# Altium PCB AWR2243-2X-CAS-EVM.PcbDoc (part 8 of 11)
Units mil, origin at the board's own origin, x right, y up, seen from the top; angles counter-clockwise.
Board outline 5118.11 x 3937.01 mil, 8 copper layers (Layer 1 - Top Layer, Layer 2 - GND, Layer 3 - Signal (Sensitive), Layer 4 - GND / Signal, Layer 5 - Signal, Layer 6 - PWR / Signal, Layer 7 - GND, Layer 8 - Bottom Layer), stack 54.8 mil thick; 629 components, 407 nets, 2243 pads, 3950 vias.
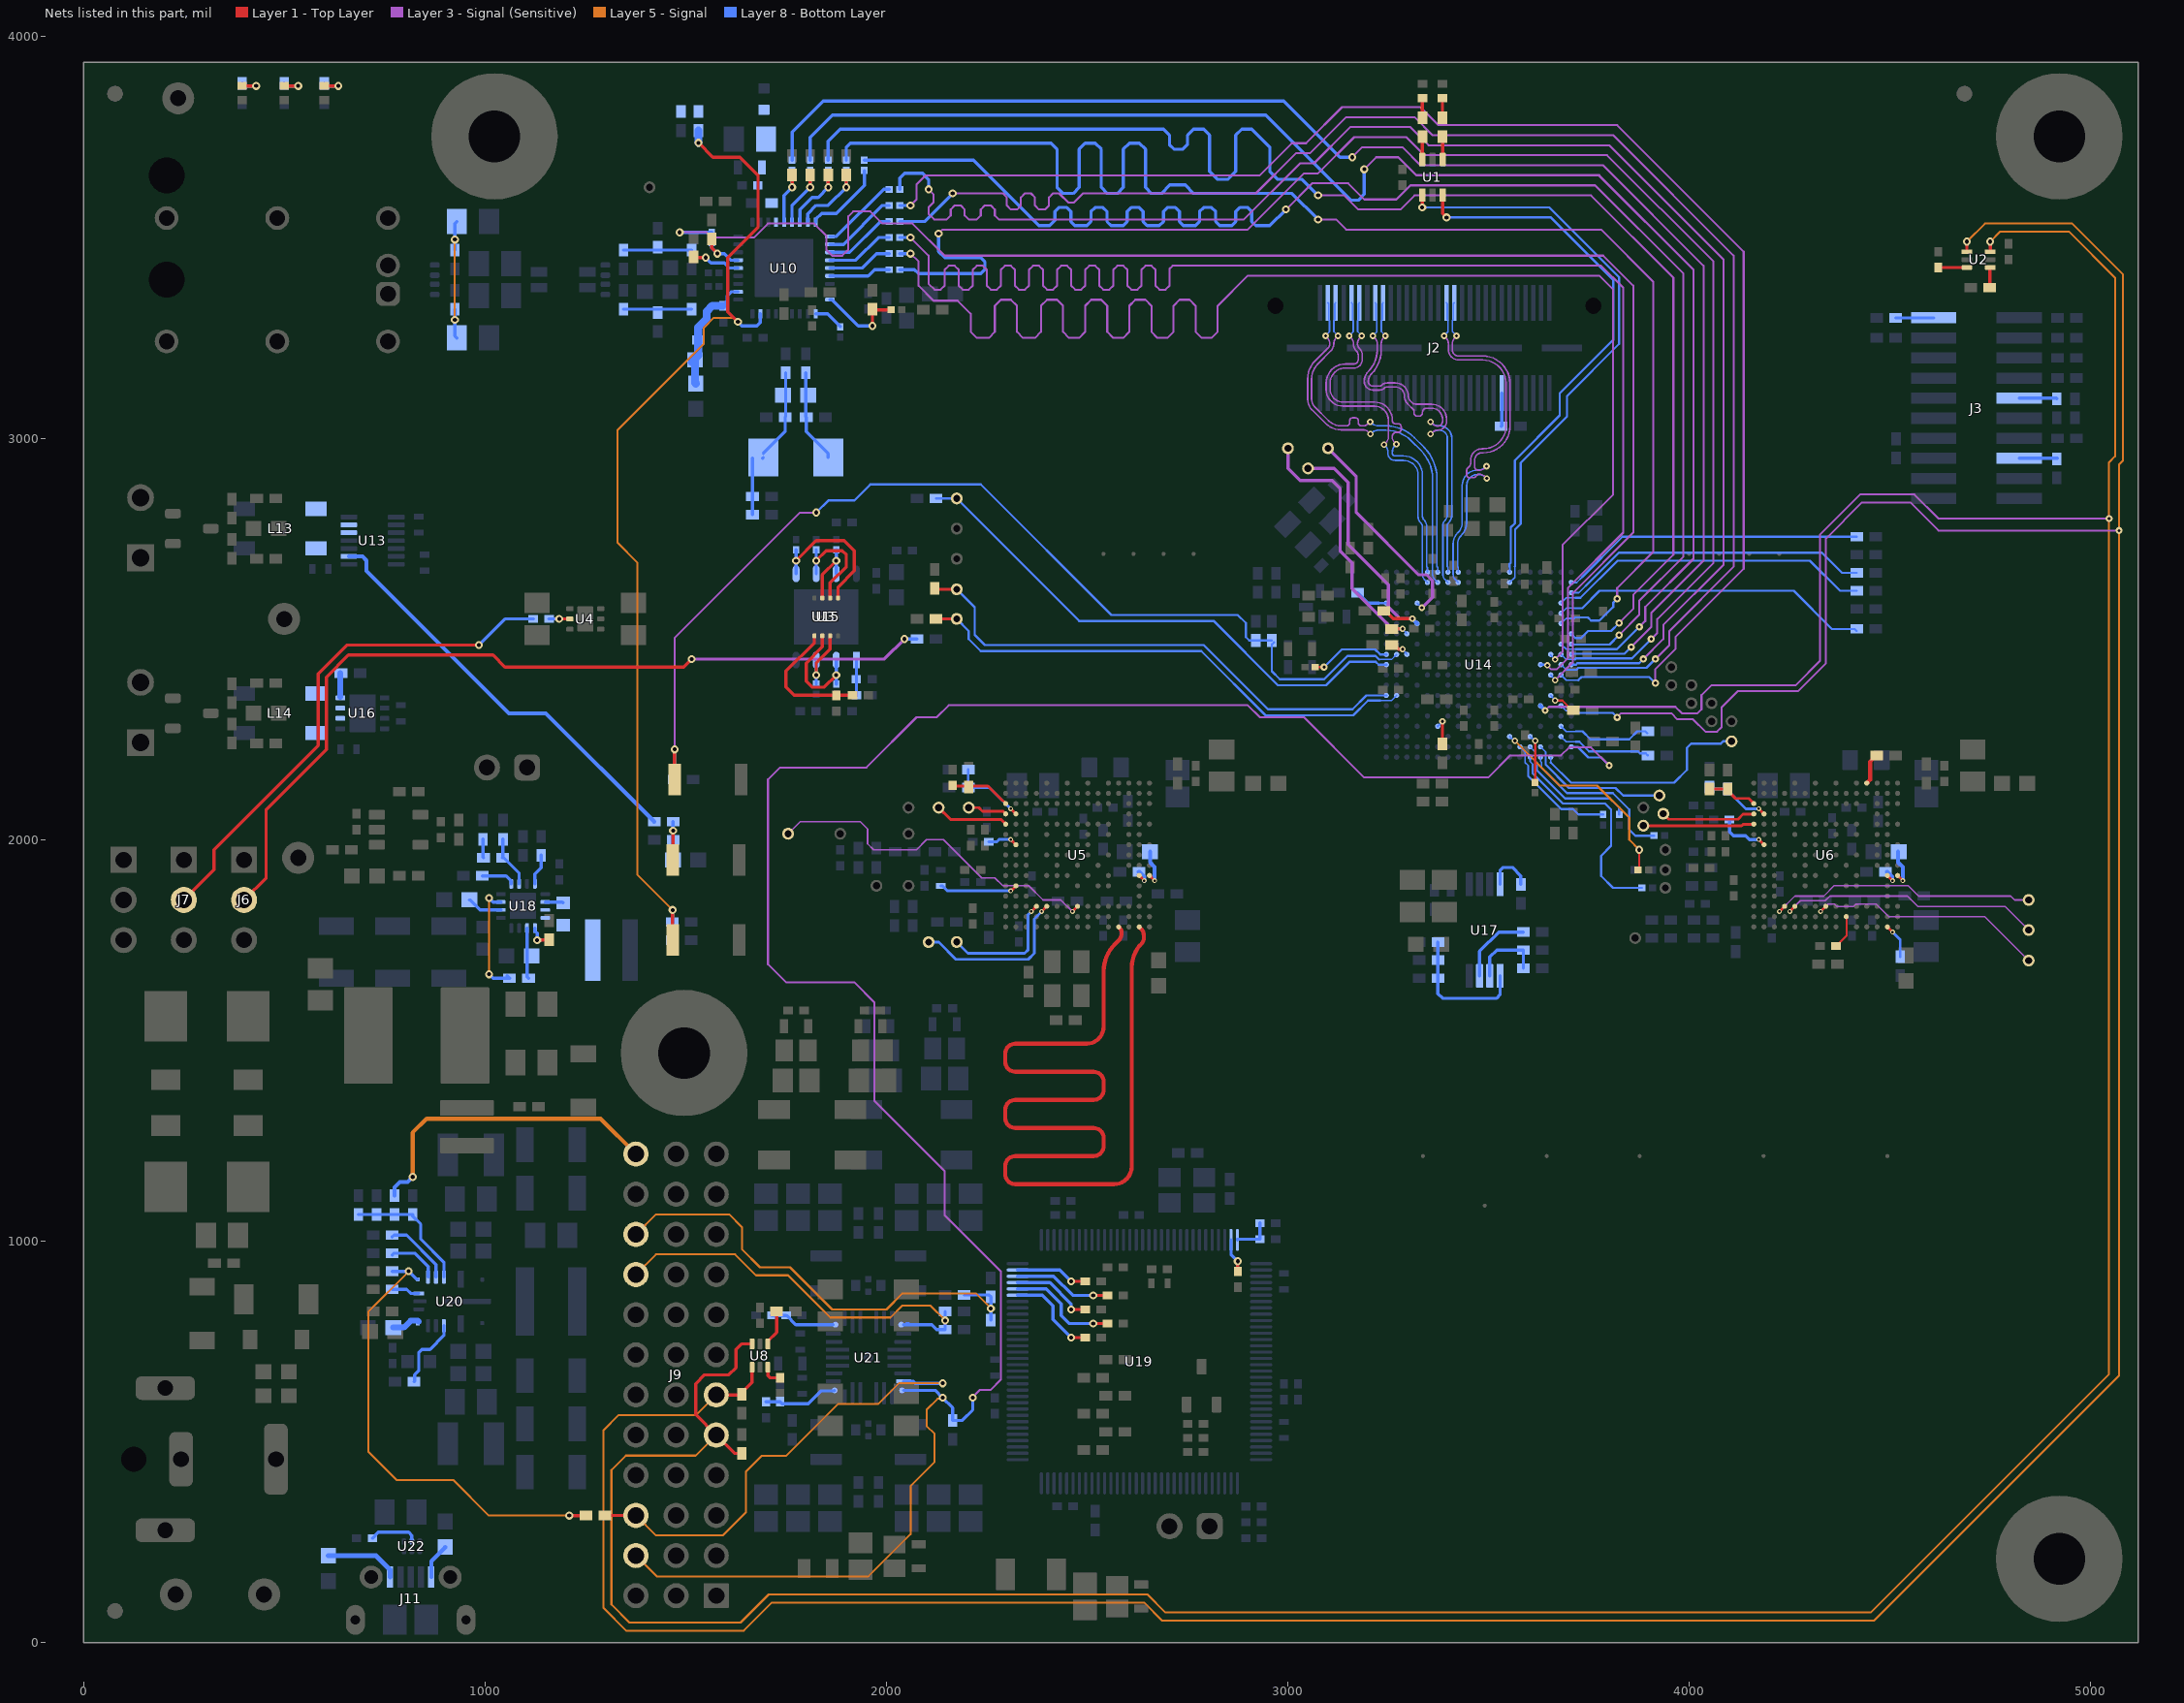
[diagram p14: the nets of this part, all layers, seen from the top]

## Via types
v1: diameter 13.78, hole 5.91, Layer 1 - Top Layer to Layer 2 - GND, tented top, 2104 vias
v2: diameter 20, hole 10, Layer 1 - Top Layer to Layer 8 - Bottom Layer, tented both sides, 831 vias
v3: diameter 7.87, hole 3.94, Layer 1 - Top Layer to Layer 2 - GND, tented top, 510 vias
v4: diameter 12, hole 6, Layer 1 - Top Layer to Layer 8 - Bottom Layer, tented both sides, 176 vias
v5: diameter 16, hole 8, Layer 1 - Top Layer to Layer 8 - Bottom Layer, tented both sides, 138 vias
v6: diameter 13.78, hole 5.91, Layer 1 - Top Layer to Layer 2 - GND, tented both sides, 88 vias
v7: diameter 18, hole 8, Layer 1 - Top Layer to Layer 8 - Bottom Layer, tented both sides, 41 vias
v8: diameter 22, hole 12, Layer 1 - Top Layer to Layer 8 - Bottom Layer, tented both sides, 36 vias
v9: diameter 19.68, hole 7.87, Layer 1 - Top Layer to Layer 8 - Bottom Layer, tented both sides, 26 vias

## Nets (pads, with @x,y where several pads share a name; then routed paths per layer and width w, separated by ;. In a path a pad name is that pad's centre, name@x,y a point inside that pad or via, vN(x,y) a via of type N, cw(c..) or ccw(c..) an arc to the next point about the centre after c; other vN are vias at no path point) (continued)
NetC98_1: C98.1 C99.2 C243.1 C244.1 FB1.2 R87.1 R88.1 U10.22
NetC100_2: C100.2 C101.1 R100.2 | length 170
  Layer 8 - Bottom Layer w8: R100.2@1345,3468.62 C101.1@1515,3468.62
NetC105_2: C105.2 C108.1 R106.1 | length 170
  Layer 8 - Bottom Layer w8: R106.1@1345,3321.38 C105.2@1515,3321.38
NetC107_2: C107.2 C110.1 C242.1 R237.2 U10.11 | length 307.4
  Layer 8 - Bottom Layer w8: C107.2@1590.24,3331.69 1591.69,3331.69 1603,3343 1603,3355 1612.94,3364.94 U10.11@1630.83,3364.94
  Layer 8 - Bottom Layer w20: C110.1@1515,3190 1531.38,3206.38 C242.1@1531.38,3245 1531.38,3276.38 1552,3297 1552,3316 1566,3330 C107.2@1592,3330 ; C110.1@1523.5,3195 1523.5,3140.11 ccw(c1528.61,3140.11) R237.2@1525,3136.5
NetC109_1: C109.1 R96.2 R101.1 R107.1 | length 346.9
  Layer 5 - Signal w5: v2(925,3295) v2(925,3495)
  Layer 8 - Bottom Layer w8: R107.1@925,3321.38 v2(925,3295) 925,3255 C109.1@930,3250 ; R101.1@925,3468.62 v2(925,3495) 925,3535 R96.2@930,3540
NetC113_1: C113.1 R115.1 R119.2 Y2.1 | length 234.5
  Layer 8 - Bottom Layer w8: R115.1@1799,3163.38 1799,3053.38 C113.1@1800.38,3052 1800.38,3016.17 1854.71,2961.84 Y2.1@1854.71,2952
NetC114_1: C114.1 R116.2 R119.1 R126.2 R129.2 Y2.2 | length 367.4
  Layer 8 - Bottom Layer w8: R129.2@1666.38,2810 R126.2@1666.38,2855 Y2.2@1666.38,2950.09 ; Y2.2@1691.38,2950.09 Y2.2@1693.29,2952 ; Y2.2@1693.29,2961.84 1747.62,3016.17 C114.1@1747.62,3052 1749,3053.38 R116.2@1749,3163.38
NetC124_1: C124.1 U14.T1 | length 81.9
  Layer 8 - Bottom Layer w5.5: 3226.58,2589.69 U14.T1@3245.08,2589.69
  Layer 8 - Bottom Layer w8: C124.1@3173.62,2615 3198.94,2589.69 3226.58,2589.69
NetC137_1: C137.1 R142.2 R143.2 S1.1 U14.L2 | length 2680.9
  Layer 1 - Top Layer w8: S1.1@1472.32,2150 v2(1472.32,2225)
  Layer 3 - Signal (Sensitive) w5: v2(1472.32,2225) 1472.32,2502.32 1785,2815 v2(1825,2815)
  Layer 8 - Bottom Layer w4: 3227.18,2448.94 3257.87,2448.94 U14.L2@3270.67,2461.73
  Layer 8 - Bottom Layer w5.5: v2(1825,2815) 1855,2845 1920,2845 1960,2885 2235,2885 2560,2560 2875,2560 2895,2540 2895,2505 2903.62,2496.38 R143.2@2920,2496.38 R142.2@2960,2496.38 ; R142.2@2965,2491.38 2960,2486.38 2960,2420 2980,2400 3090,2400 3148,2458 3218.12,2458 3227.18,2448.94
  Layer 8 - Bottom Layer w8: C137.1@1471.38,2150 1472.32,2150.94 v2(1472.32,2225)
NetC144_1: C144.1 R177.2 U18.14 | length 131.3
  Layer 8 - Bottom Layer w8: C144.1@1045,2001.38 1045,1956.38 R177.2@1043.62,1955 1047.56,1955 1085,1917.56 1085,1890.28 U18.14@1085.16,1890.12
NetC145_1: C145.1 R177.1 | length 46.9
  Layer 8 - Bottom Layer w8: C145.1@995,2001.38 995,1956.38 R177.1@996.38,1955
NetC150_1: C150.1 U6.A10 | length 94.8
  Layer 1 - Top Layer w7: U6.A10@4518.5,1910.83 v4(4531.3,1898.03)
  Layer 8 - Bottom Layer w10: C150.1@4519.88,1970 4519.88,1943.5 4531.3,1932.09 v4(4531.3,1898.03)
NetC151_1: C151.1 U5.A10 | length 94.8
  Layer 1 - Top Layer w7: U5.A10@2655.12,1910.83 v4(2667.91,1898.03)
  Layer 8 - Bottom Layer w10: C151.1@2656.5,1970 2656.5,1943.5 2667.91,1932.09 v4(2667.91,1898.03)
NetC152_1: C152.1 R163.1 R169.1 S2.1 | length 168.1
  Layer 1 - Top Layer w8: S2.1@1467.32,1950 1468.62,1951.3 v2(1468.62,2022.5)
  Layer 8 - Bottom Layer w8: C152.1@1468.5,1950 1468.62,1950.12 R169.1@1468.62,2000 v2(1468.62,2022.5) R163.1@1468.62,2045
NetC154_1: C154.1 U6.B10 | length 46
  Layer 1 - Top Layer w7: U6.B10@4492.91,1910.83 v4(4505.71,1898.03)
  Layer 8 - Bottom Layer w10: C154.1@4492.01,1920 4493.39,1920 4505.33,1908.06 v4@4505.33,1898.41
NetC155_1: C155.1 U5.B10 | length 46.5
  Layer 1 - Top Layer w7: U5.B10@2629.53,1910.83 v4(2642.32,1898.03)
  Layer 8 - Bottom Layer w10: C155.1@2628.62,1920 2630,1920 2641.94,1908.06 2641.94,1898.41 v4(2642.32,1898.03)
NetC162_1: C162.1 U18.10 | length 88.7
  Layer 8 - Bottom Layer w8: C162.1@961.5,1850 962.48,1850 987.32,1825.16 U18.10@1039.88,1825.16
NetC167_1: C167.1 L15.2 U18.3 U18.4
NetC167_2: C167.2 U18.2 | length 45.8
  Layer 8 - Bottom Layer w8: U18.2@1150.12,1844.84 1192.72,1844.84 C167.2@1195,1842.56
NetC182_2: C182.2 R87.2 R194.2 S3.2 U10.8 | length 2549.3
  Layer 1 - Top Layer w8: S3.2@1467.32,1750 v2(1467.32,1825) ; v2(1531.77,3736) 1567.77,3700 1635,3700 1680,3655 1680,3525 1605,3450 1605,3315 v2(1630,3290)
  Layer 5 - Signal w5: v2(1467.32,1825) 1380,1912.32 1380,2690 1330,2740 1330,3020 1545,3235 1545,3275 1570,3300 1620,3300 v2(1630,3290)
  Layer 8 - Bottom Layer w8: C182.2@1466.38,1750 1467.32,1750.94 v2(1467.32,1825) ; v2(1630,3290) 1640,3280 1677.35,3280 1685.94,3288.59 U10.8@1685.94,3309.83
  Layer 8 - Bottom Layer w20: v2(1531.77,3736) R87.2@1531.77,3766.38
NetC183_1: C183.1 R204.2 U18.6 | length 126.4
  Layer 8 - Bottom Layer w8: U18.6@1104.84,1779.88 1104.84,1658.78 R204.2@1108.62,1655
NetC208_2: C208.2 R212.1 U19.96 | length 98
  Layer 8 - Bottom Layer w8: U19.96@2874.09,1003.15 2874.09,1004.94 2874.16,1005 C208.2@2930.31,1005 R212.1@2930.31,1045
NetC211_2: C211.2 R220.1 U21.25 | length 164.1
  Layer 8 - Bottom Layer w8: R220.1@1714.68,815 C211.2@1750.31,815 ; C211.2@1748.35,814.33 1751.67,814.33 1774.31,791.69 U21.25@1867.4,791.69
NetC212_2: C212.2 U20.6 | length 71.4
  Layer 8 - Bottom Layer w15: C212.2@771.5,785 798,785 815,802 833,802 835,800
NetC223_2: C223.2 R223.1 U21.17 | length 187.5
  Layer 8 - Bottom Layer w8: R223.1@1699.68,600 1699.84,600.16 1734.84,600.16 C223.2@1735,600.31 1740.31,595 1805,595 1837.21,627.21 1869.87,627.21 U21.17@1871.03,628.37
NetD1_1: D1.1 R1.1 | length 48.7
  Layer 1 - Top Layer w8: R1.1@3335,3798.62 D1.1@3335,3847.28
NetD2_1: D2.1 R2.1 | length 48.7
  Layer 1 - Top Layer w8: R2.1@3385,3798.62 D2.1@3385,3847.28
NetD3_1: D3.1 R86.1 | length 72.4
  Layer 1 - Top Layer w8: D3.1@395,3877.72 v2(430,3877.72)
  Layer 8 - Bottom Layer w8: R86.1@395,3883.62 400.91,3877.72 v2(430,3877.72)
NetD4_1: D4.1 R85.1 | length 72.4
  Layer 1 - Top Layer w8: D4.1@500,3877.72 v2(535,3877.72)
  Layer 8 - Bottom Layer w8: R85.1@500,3883.62 505.91,3877.72 v2(535,3877.72)
NetD5_2: D5.2 R84.1 | length 72.4
  Layer 1 - Top Layer w8: D5.2@600,3877.72 v2(635,3877.72)
  Layer 8 - Bottom Layer w8: R84.1@600,3883.62 605.91,3877.72 v2(635,3877.72)
NetJ2_13: J2.13 R122.1 | length 82.6
  Layer 8 - Bottom Layer w8: R122.1@3531.38,3030 3532.32,3030.94 J2.13@3532.32,3112.2
NetJ6_2: J6.2 R146.1 | length 2175.5
  Layer 1 - Top Layer w8: J6.2@400,1850 455,1905 455,2075 605,2225 605,2405 660,2460 1020,2460 1050,2430 1495,2430 v2(1515,2450)
  Layer 3 - Signal (Sensitive) w8: v2(1515,2450) 1995,2450 v2(2045,2500)
  Layer 8 - Bottom Layer w8: v2(2045,2500) R146.1@2076.38,2500
NetJ7_2: J7.2 R144.1 | length 1294
  Layer 1 - Top Layer w8: J7.2@250,1850 325,1925 325,1975 585,2235 585,2413.28 656.72,2485 v2(985,2485)
  Layer 8 - Bottom Layer w8: v2(985,2485) 1050,2550 R144.1@1120.31,2550
NetJ9_30: J9.30 R216.1 R219.1 R241.1 | length 1193.3
  Layer 5 - Signal w5: J9.30@1375.98,1017.01 1425.98,1067 1608,1067 1640,1035 1640,980 1685,935 1760,935 1865,830 2000,830 2040,870 2222.5,870 v2(2260,832.5)
  Layer 8 - Bottom Layer w8: R241.1@2193.62,866 2255.38,866 R216.1@2260,861.38 v2(2260,832.5) R219.1@2260,803.62
NetJ11_1: J11.1 R229.1 | length 89.8
  Layer 8 - Bottom Layer w10: J11.1@866.18,163.15 866.18,202.7 901,237.52 R229.1@901,238.5
NetJ11_5: J11.5 R233.2 | length 186.5
  Layer 8 - Bottom Layer w12: R233.2@610,216.5 728.5,216.5 763.82,181.18 J11.5@763.82,163.15
NetL13_1: L13.1 U13.13
NetL13_2: L13.2 U13.12
NetL14_1: L14.1 U16.7
NetL14_2: L14.2 U16.6
NetR1_2: R1.2 U1.6 | length 57.3
  Layer 1 - Top Layer w8: U1.6@3334.41,3694.29 3334.7,3694.59 3334.7,3751.08 R1.2@3335,3751.38
NetR2_2: R2.2 U1.4 | length 57.3
  Layer 1 - Top Layer w8: R2.2@3385,3751.38 3385.3,3751.08 3385.3,3694.59 U1.4@3385.59,3694.29
NetR10_2: R10.2 U2.3 | length 70.9
  Layer 1 - Top Layer w8: R10.2@4620,3425.31 U2.3@4690.87,3425.32
NetR11_1: R11.1 R16.2 U10.36 | length 211.8
  Layer 1 - Top Layer w8: v2(1965,3280) R11.1@1965,3311.38 ; R11.1@1965,3321.38 1966.38,3320 R16.2@2012.01,3320
  Layer 8 - Bottom Layer w8: U10.36@1859.17,3345.26 1864.74,3345.26 1930,3280 v2(1965,3280)
NetR12_1: R12.1 U2.4 | length 51.6
  Layer 1 - Top Layer w8: U2.4@4749.13,3425.32 4748.56,3424.74 R12.1@4748.56,3375.57 ; R12.1@4748.56,3375.57 R12.1@4747.99,3375 R12.1@4748.56,3375.57
NetR25_1: R25.1 TP8.1 U14.G1 | length 1299.9
  Layer 1 - Top Layer w8: R25.1@2123.62,2623.94 TP8.1@2175,2623.94
  Layer 8 - Bottom Layer w5.5: TP8.1@2175,2623.94 2220,2578.94 2220,2510 2245,2485 2790.15,2485 2950.15,2325 3160.83,2325 3195.2,2359.37 U14.G1@3245.08,2359.37
NetR27_2: R27.2 TP4.1 U14.P4 | length 634.4
  Layer 1 - Top Layer w8: R27.2@3238.62,2570 3242.56,2570 3262.19,2550.37 v5(3309.98,2550.37)
  Layer 3 - Signal (Sensitive) w8: TP4.1@3050,2925 3115,2925 3150,2890 3150,2735 3250,2635 3250,2580 3279.63,2550.37 v5(3309.98,2550.37)
  Layer 8 - Bottom Layer w10: v5(3309.98,2550.37) U14.P4@3321.85,2538.5
NetR29_1: R29.1 TP10.1 U14.G2 | length 1278.6
  Layer 1 - Top Layer w8: R29.1@2123.62,2550 TP10.1@2175,2550
  Layer 8 - Bottom Layer w4: 3229.58,2346.57 3257.87,2346.57 U14.G2@3270.67,2359.37
  Layer 8 - Bottom Layer w5.5: TP10.1@2175,2550 2205,2520 2205,2500 2235,2470 2783.93,2470 2943.93,2310 3162.71,2310 3199.29,2346.57 3229.58,2346.57
NetR30_2: R30.2 TP2.1 U14.N3 | length 673.8
  Layer 1 - Top Layer w8: R30.2@3258.62,2525 3259.33,2525.71 v5(3285.61,2525.71)
  Layer 3 - Signal (Sensitive) w8: TP2.1@3000,2975 3000,2925 3030,2895 3110,2895 3130,2875 3130,2720 3160,2690 3160,2625 3259.29,2525.71 v5(3285.61,2525.71)
  Layer 8 - Bottom Layer w4: v5(3285.61,2525.71) U14.N3@3296.26,2512.91
NetR31_1: R31.1 U14.L3 | length 48
  Layer 1 - Top Layer w8: R31.1@3258.62,2485 3265,2485 3275.47,2474.53 v5(3285.61,2474.53)
  Layer 8 - Bottom Layer w4: v5(3285.61,2474.53) U14.L3@3296.26,2461.73
NetR32_1: R32.1 U14.L1 | length 200.4
  Layer 1 - Top Layer w5.5: R32.1@3067.99,2430 v7(3090,2430)
  Layer 8 - Bottom Layer w5.5: v7(3090,2430) 3134,2474 3217.12,2474 3229.39,2461.73 U14.L1@3245.08,2461.73
NetR34_2: R34.2 U14.G17 | length 72
  Layer 1 - Top Layer w5.5: v5(3665.18,2346.58) 3683.42,2346.58 3707.31,2322.69 R34.2@3710.59,2322.69
  Layer 8 - Bottom Layer w4: U14.G17@3654.53,2359.37 v5(3665.18,2346.58)
NetR37_2: R37.2 U14.D6 | length 72.7
  Layer 1 - Top Layer w8: v5(3384.9,2294.47) 3384.95,2294.42 3384.95,2238.67 R37.2@3385,2238.62
  Layer 8 - Bottom Layer w5.5: U14.D6@3373.03,2282.6 v5(3384.9,2294.47)
NetR39_2: R39.2 U6.D1 | length 83
  Layer 1 - Top Layer w10: U6.D1@4441.73,2141.14 4450,2149.41 4450,2193.62 R39.2@4466.38,2210 ; R39.2@4462.44,2205 R39.2@4466.38,2205
NetR40_1: R40.1 R43.1 U5.R3 | length 150.1
  Layer 1 - Top Layer w7: R43.1@2165,2133.94 2252.87,2133.94 2284.05,2102.76 U5.R3@2296.85,2089.96
NetR41_1: R41.1 R42.1 U6.R3 | length 127.6
  Layer 1 - Top Layer w7: R41.1@4050,2126.38 R42.1@4095,2126.38 4095,2122.44 4114.68,2102.76 4147.44,2102.76 U6.R3@4160.24,2089.96
NetR47_1: R47.1 U14.C15 | length 120.5
  Layer 1 - Top Layer w5.5: R47.1@3615,2142.99 3616.14,2144.13 v5(3616.14,2246.35)
  Layer 8 - Bottom Layer w4: U14.C15@3603.35,2257.01 v5(3616.14,2246.35)
NetR54_1: R54.1 U14.C13 | length 522.5
  Layer 1 - Top Layer w5.5: R54.1@3872.01,1925 3875,1927.99 v2(3875,1975)
  Layer 5 - Signal w5.5: v5(3564.96,2246.35) 3676.32,2135 3770,2135 3850,2055 3850,2000 v2(3875,1975)
  Layer 8 - Bottom Layer w4: U14.C13@3552.17,2257.01 v5(3564.96,2246.35)
NetR58_1: R58.1 U18.5 | length 62.7
  Layer 1 - Top Layer w8: v2(1130,1750) 1158.62,1750 R58.1@1160,1751.38
  Layer 8 - Bottom Layer w8: U18.5@1124.53,1779.88 1124.53,1772.47 1130,1767 v2(1130,1750)
NetR59_2: R59.2 U6.F14 | length 84.8
  Layer 1 - Top Layer w5: R59.2@4364.69,1735 4365,1735 4391.55,1761.55 U6.F14@4391.55,1808.46
NetR64_2: R64.2 U19.95 | length 85.4
  Layer 1 - Top Layer w8: R64.2@2875,924.69 v2(2875,950)
  Layer 8 - Bottom Layer w8: U19.95@2858.34,1003.15 2858.35,966.65 v2(2875,950)
NetR65_2: R65.2 U19.63 | length 180.2
  Layer 1 - Top Layer w8: v2(2460,900) R65.2@2495.31,900
  Layer 8 - Bottom Layer w8: U19.63@2326.85,928.35 2431.65,928.35 v2(2460,900)
NetR67_2: R67.2 U19.62 | length 243.2
  Layer 1 - Top Layer w8: v2(2515,865) R67.2@2550.31,865
  Layer 8 - Bottom Layer w8: U19.62@2326.85,912.6 2416.4,912.6 2464,865 v2(2515,865)
NetR69_1: R69.1 U19.61 | length 204.4
  Layer 1 - Top Layer w8: v2(2460,830) R69.1@2495.32,830
  Layer 8 - Bottom Layer w8: U19.61@2326.85,896.85 2407.15,896.85 2460,844 v2(2460,830)
NetR70_2: R70.2 U8.4 | length 89.9
  Layer 1 - Top Layer w8: U8.4@1704.68,744.13 1704.68,751.42 1726.38,773.11 R70.2@1726.38,825
NetR71_1: R71.1 U19.60 | length 276.1
  Layer 1 - Top Layer w8: v2(2515,795) R71.1@2550.32,795
  Layer 8 - Bottom Layer w8: U19.60@2326.85,881.1 2397.9,881.1 2435,844 2435,815 2455,795 v2(2515,795)
NetR72_2: R72.2 U19.59 | length 232
  Layer 1 - Top Layer w8: v2(2460,760) R72.2@2495.31,760
  Layer 8 - Bottom Layer w8: U19.59@2326.85,865.35 2388.65,865.35 2415,839 2415,805 v2(2460,760)
NetR74_2: R74.2 U8.3 | length 53.6
  Layer 1 - Top Layer w8: U8.3@1704.68,685.87 1704.68,664.69 1709.69,659.69 R74.2@1735,659.69
NetR89_2: R89.2 U10.27 | length 200.3
  Layer 8 - Bottom Layer w8: U10.27@1823.74,3538.17 1823.74,3545.06 1838.68,3560 1875,3560 1945,3630 R89.2@1945,3667.01
NetR94_2: R94.2 U10.28 | length 196.4
  Layer 8 - Bottom Layer w8: U10.28@1859.17,3502.74 1875.74,3502.74 1993,3620 R94.2@2007.01,3620
NetR95_2: R95.2 U10.29 | length 188
  Layer 8 - Bottom Layer w8: U10.29@1859.17,3483.06 1893.06,3483.06 1990,3580 R95.2@2007.01,3580
NetR97_2: R97.2 U10.30 | length 179.6
  Layer 8 - Bottom Layer w8: U10.30@1859.17,3463.37 1908.37,3463.37 1985,3540 R97.2@2007.01,3540
NetR99_2: R99.2 U10.31 | length 171.2
  Layer 8 - Bottom Layer w8: U10.31@1859.17,3443.69 1923.68,3443.69 1980,3500 R99.2@2007.01,3500
NetR102_2: R102.2 U10.32 | length 162.7
  Layer 8 - Bottom Layer w8: U10.32@1859.17,3424 1939,3424 1975,3460 R102.2@2007.01,3460
NetR104_2: R104.2 U10.33 | length 154.3
  Layer 8 - Bottom Layer w8: U10.33@1859.17,3404.32 1954.31,3404.32 1970,3420 R104.2@2007.01,3420
NetR112_2: R112.2 U10.1 | length 74.9
  Layer 8 - Bottom Layer w8: U10.1@1823.74,3309.83 1853.95,3309.83 1885,3278.78 R112.2@1885,3277.99
NetR127_1: R127.1 TP5.1 U14.K1 | length 1340.9
  Layer 8 - Bottom Layer w5.5: R127.1@2123.62,2850 TP5.1@2175,2850 2480,2545 2815,2545 2975,2385 3095,2385 3153,2443 3218.91,2443 3225.77,2436.14 U14.K1@3245.08,2436.14
NetR131_2: R131.2 U14.V19 | length 757.9
  Layer 8 - Bottom Layer w4: U14.V19@3705.71,2640.87 3719.31,2640.87 3732.7,2654.25
  Layer 8 - Bottom Layer w5.5: 3732.7,2654.25 3833.45,2755 R131.2@4416.38,2755
NetR139_2: R139.2 U14.U19 | length 772.7
  Layer 8 - Bottom Layer w4: U14.U19@3705.71,2615.28 3724.28,2615.28 3741.25,2632.25
  Layer 8 - Bottom Layer w5.5: 3741.25,2632.25 3824,2715 4330,2715 4380,2665 R139.2@4416.38,2665
NetR140_2: R140.2 U14.T18 | length 810.9
  Layer 8 - Bottom Layer w4: U14.T18@3680.12,2589.69 3692.91,2602.48 3715.34,2602.48
  Layer 8 - Bottom Layer w5.5: 3715.34,2602.48 3728.48,2602.48 3821,2695 4300,2695 4375,2620 R140.2@4416.38,2620
NetR144_2: R144.2 U4.2 | length 51.9
  Layer 1 - Top Layer w8: v2(1185,2550) U4.2@1211.61,2550
  Layer 8 - Bottom Layer w8: R144.2@1159.68,2550 v2(1185,2550)
NetR145_2: R145.2 U14.R18 | length 800.8
  Layer 8 - Bottom Layer w4: U14.R18@3680.12,2564.09 3692.91,2576.89 3714.6,2576.89
  Layer 8 - Bottom Layer w5.5: 3714.6,2576.89 3732.89,2576.89 3776,2620 4260,2620 4355,2525 4411.38,2525 R145.2@4416.38,2520
NetR147_2: R147.2 U16.8 | length 59
  Layer 8 - Bottom Layer w15: U16.8@639.76,2356 R147.2@639.76,2415
NetR153_2: R153.2 U14.D18 | length 238.7
  Layer 8 - Bottom Layer w4: U14.D18@3680.12,2282.6 3692.91,2269.8 3717.49,2269.8
  Layer 8 - Bottom Layer w5.5: 3717.49,2269.8 3733.69,2269.8 3753.5,2250 3850,2250 3870,2270 3890,2270 R153.2@3895,2265
NetR154_2: R154.2 U14.C18 | length 235.7
  Layer 8 - Bottom Layer w4: U14.C18@3680.12,2257.01 3692.91,2244.21 3717.49,2244.21
  Layer 8 - Bottom Layer w5.5: 3717.49,2244.21 3725.61,2244.21 3749.83,2220 3872,2220 3877,2215 3891.38,2215 R154.2@3896.38,2210
NetR155_1: R155.1 R156.1 U6.P4 | length 163.8
  Layer 1 - Top Layer w7: v4(4173.03,2077.17) U6.P4@4185.83,2064.37
  Layer 8 - Bottom Layer w7: R156.1@4050,2126.38 R155.1@4095,2126.38 4095,2122.44 4140.28,2077.17 v4(4173.03,2077.17)
NetR157_1: R157.1 R158.1 U5.P4 | length 191
  Layer 1 - Top Layer w7: v4(2309.64,2077.17) U5.P4@2322.44,2064.37
  Layer 8 - Bottom Layer w7: R157.1@2203.62,2175 R158.1@2203.62,2130 2256.81,2130 v4(2309.64,2077.17)
NetR161_1: R161.1 U14.B15 | length 325.8
  Layer 8 - Bottom Layer w4: U14.B15@3603.35,2231.42 3616.14,2218.62 3616.14,2196.28 3620.84,2191.58 3620.84,2172.16
  Layer 8 - Bottom Layer w5.5: 3620.84,2172.16 3690,2103 3741,2103 3802,2103 3825,2080 R161.1@3825,2062.99
NetR162_1: R162.1 U14.B14 | length 307.8
  Layer 8 - Bottom Layer w4: U14.B14@3577.75,2231.42 3590.55,2218.62 3590.55,2191.97 3597.55,2185.62 3598.31,2184.87 3598.31,2158.69
  Layer 8 - Bottom Layer w5.5: 3598.31,2158.69 3680.75,2076.25 3709.87,2076.25 3723.13,2062.99 R162.1@3785,2062.99
NetR163_2: R163.2 U13.9 | length 1049.1
  Layer 8 - Bottom Layer w10: U13.9@660.94,2705.63 695,2705.63 705,2695.63 705,2670 1060,2315 1151.38,2315 R163.2@1421.38,2045
NetR165_1: R165.1 U6.P7 | length 129.2
  Layer 1 - Top Layer w7: v4(4173.03,2000.39) U6.P7@4185.83,1987.6
  Layer 8 - Bottom Layer w8: R165.1@4100,2050 4100,2020 4110,2010 4140,2010 4149.61,2000.39 v4(4173.03,2000.39)
NetR166_2: R166.2 U18.16 | length 77.7
  Layer 8 - Bottom Layer w8: U18.16@1124.53,1890.12 1124.53,1914.53 1140,1930 R166.2@1140,1961.38
NetR168_1: R168.1 U14.A16 | length 407.2
  Layer 8 - Bottom Layer w4: U14.A16@3629.13,2205.64 U14.A16@3628.94,2205.83 3628.94,2195.73 3631,2193.66 ; 3631.74,2193.17 3631.74,2179.26 3641.93,2169.07
  Layer 8 - Bottom Layer w5.5: 3641.93,2169.07 3695,2116 3809,2116 3850,2075 3850,2025 3865,2010 3911.93,2010 R168.1@3912.24,2010.31
NetR170_1: R170.1 U5.P7 | length 75
  Layer 1 - Top Layer w7: v4(2309.64,2000.39) U5.P7@2322.44,1987.6
  Layer 8 - Bottom Layer w7: R170.1@2255,1995 2275,1995 2280.39,2000.39 v4(2309.64,2000.39)
NetR182_1: R182.1 U18.13 | length 84.2
  Layer 8 - Bottom Layer w8: R182.1@993.62,1910 1052.68,1910 1065.47,1897.2 U18.13@1065.47,1890.12
NetR183_2: R183.2 U5.P11 | length 197.9
  Layer 1 - Top Layer w7: v4(2309.65,1872.44) U5.P11@2322.44,1885.24
  Layer 8 - Bottom Layer w7: R183.2@2135,1885 2139.5,1885 2152.06,1872.44 v4(2309.65,1872.44)
NetR184_2: R184.2 U17.8 | length 119.1
  Layer 8 - Bottom Layer w8: U17.8@3528.38,1889.17 3528.38,1923.38 3536,1931 3559,1931 3580,1910 R184.2@3580,1888.62
NetR187_1: R187.1 U14.A15 | length 565.7
  Layer 8 - Bottom Layer w4: U14.A15@3603.35,2205.83 3603.35,2194.75 3603.45,2194.75 3609.43,2188.76 3609.43,2171.05
  Layer 8 - Bottom Layer w5.5: 3609.43,2171.05 3609.43,2165.57 3685,2090 3790,2090 3805,2075 3805,1985 3780,1960 3780,1910 3810,1880 R187.1@3882.01,1880
NetR195_2: R195.2 U17.3 | length 190.3
  Layer 8 - Bottom Layer w8: U17.3@3477.2,1660.83 3477.2,1722.2 3525,1770 R195.2@3586.38,1770
NetR198_2: R198.2 R201.1 R203.1 U17.1 | length 339
  Layer 8 - Bottom Layer w8: R198.2@3373.62,1745 R201.1@3373.62,1700 R203.1@3373.62,1655 3373.62,1616.38 3385,1605 3520,1605 3528.39,1613.39 U17.1@3528.38,1660.83
NetR199_1: R199.1 R202.1 U17.2 | length 182.7
  Layer 8 - Bottom Layer w8: U17.2@3502.79,1660.83 3502.8,1707.8 3520,1725 R199.1@3586.38,1725 R202.1@3586.38,1680
NetR200_2: R200.2 U6.B15 | length 87.5
  Layer 1 - Top Layer w7: U6.B15@4492.91,1782.87 v4(4505.71,1770.08)
  Layer 8 - Bottom Layer w7: v4(4505.71,1770.08) 4525,1750.79 R200.2@4525,1708.62
NetR204_1: R204.1 U18.11 | length 288.6
  Layer 5 - Signal w5: v2(1010,1665) v2(1010,1855)
  Layer 8 - Bottom Layer w8: v2(1010,1665) 1020,1655 R204.1@1061.38,1655 R204.1@1055.01,1661.37 ; v2(1010,1855) 1020.16,1844.84 U18.11@1039.88,1844.84
NetR205_1: R205.1 R206.1 R207.1 R208.2 U20.13 | length 323
  Layer 8 - Bottom Layer w8: R207.1@685,1066.38 R206.1@730,1066.38 R205.1@775,1066.38 R208.2@820,1066.38 820,1062.44 840,1042.44 840,1005 897.74,947.26 U20.13@897.73,910.55
NetR213_2: R213.2 U20.12 | length 173.2
  Layer 8 - Bottom Layer w8: R213.2@768.62,1010 773.62,1015 805,1015 878.05,941.95 U20.12@878.05,910.55
NetR214_2: R214.2 U20.11 | length 131.7
  Layer 8 - Bottom Layer w8: R214.2@768.62,965 773.62,970 825,970 858.37,936.63 U20.11@858.37,910.55
NetR217_2: R217.2 U20.9 | length 70.9
  Layer 8 - Bottom Layer w8: R217.2@768.62,880 805,880 815.16,869.84 835.06,869.84 U20.9@835.21,869.68
NetR232_2: R232.2 U22.5 | length 123
  Layer 8 - Bottom Layer w8: R232.2@719.68,260 734.69,275 810,275 818,267 U22.5@818,251.81
NetTP3_1: TP3.1 U14.T4 | length 544.3
  Layer 3 - Signal (Sensitive) w8: TP3.1@3100,2975 3170,2905 3170,2815 3325,2660 3345,2660 3360,2645 3360,2604.1 v5(3333.72,2577.82)
  Layer 8 - Bottom Layer w4: U14.T4@3321.85,2589.69 v5(3333.72,2577.82)
NetTP21_1: TP21.1 U5.R5 | length 183.9
  Layer 1 - Top Layer w7: TP21.1@2130,2080 2160,2050 2285.63,2050 U5.R5@2296.85,2038.78
NetTP22_1: TP22.1 U5.R4 | length 98.3
  Layer 1 - Top Layer w7: TP22.1@2205,2080 2230,2080 2239.39,2070.61 2290.61,2070.61 U5.R4@2296.85,2064.37
NetTP24_1: TP24.1 U6.R4 | length 241.7
  Layer 1 - Top Layer w7: TP24.1@3935,2070 3940.24,2064.76 3940.24,2059.53 3948.76,2051 4121,2051 4133.44,2063.44 4159.3,2063.44 U6.R4@4160.24,2064.37
NetTP25_1: TP25.1 U6.R5 | length 276.6
  Layer 1 - Top Layer w7: TP25.1@3885.23,2035 4130,2035 4133.44,2038.44 4159.89,2038.44 U6.R5@4160.24,2038.78
NetTP34_1: TP34.1 U6.M13 | length 680
  Layer 1 - Top Layer w7: v4(4224.21,1821.26) U6.M13@4237.01,1834.06
  Layer 3 - Signal (Sensitive) w4: v4(4224.21,1821.26) 4262.6,1859.65 4334.65,1859.65 4360.24,1885.24 4545,1885.24 4570.59,1859.65 4800.35,1859.65 4810,1850 TP34.1@4845,1850
NetTP35_1: TP35.1 U5.H13 | length 873.6
  Layer 1 - Top Layer w7: v4(2463.19,1821.26) U5.H13@2475.98,1834.06
  Layer 3 - Signal (Sensitive) w4: TP35.1@1755.13,2015 1785.13,2045 1935,2045 1953,2027 1953,1990 1968,1975 2075,1975 2100,2000 2142,2000 2237,1905 2270,1905 2289.76,1885.24 2354.76,1885.24 2390,1850 2434.45,1850 v4(2463.19,1821.26)
NetTP36_1: TP36.1 U6.L13 | length 669.3
  Layer 1 - Top Layer w7: v4(4249.8,1821.26) U6.L13@4262.6,1834.06
  Layer 3 - Signal (Sensitive) w4: v4(4249.8,1821.26) 4276.54,1848 4338,1848 4349.65,1859.65 4543.01,1859.65 4568.6,1834.06 4785.94,1834.06 TP36.1@4845,1775 TP36.1@4850,1775
NetTP38_1: TP38.1 U5.M13 | length 310
  Layer 1 - Top Layer w7: v4(2360.83,1821.26) U5.M13@2373.62,1834.06
  Layer 8 - Bottom Layer w7: TP38.1@2175,1745.23 2203.23,1717 2344,1717 2353,1726 2353,1813.43 v4(2360.83,1821.26)
NetTP39_1: TP39.1 U5.L13 | length 417
  Layer 1 - Top Layer w7: v4(2386.42,1821.26) U5.L13@2399.21,1834.06
  Layer 8 - Bottom Layer w7: TP39.1@2105,1745 2105.26,1744.74 2130.26,1744.74 2173,1702 2353,1702 2368,1717 2368,1802.84 v4(2386.42,1821.26)
NetTP40_1: TP40.1 U6.H13 | length 612.5
  Layer 1 - Top Layer w7: v4(4326.58,1821.26) U6.H13@4339.37,1834.06
  Layer 3 - Signal (Sensitive) w4: v4(4326.58,1821.26) 4345.32,1840 4361.25,1840 4367.2,1834.06 4409.06,1834.06 4415,1840 4465,1840 4496.54,1808.46 4735.77,1808.46 TP40.1@4845,1699.23 TP40.1@4850,1699.23
NetU1_1: U1.1 U14.V13 | length 1466.6
  Layer 1 - Top Layer w8: v2(3334.41,3575) U1.1@3334.41,3605.71
  Layer 8 - Bottom Layer w4: U14.V13@3552.17,2640.87 3564.96,2653.66 3564.96,2680.69
  Layer 8 - Bottom Layer w5: 3564.96,2680.69 3566.11,2681.84 3566.11,2772.99
  Layer 8 - Bottom Layer w5.5: v2(3334.41,3575) 3651.21,3575 3825,3401.21 3825,3235 3695,3105 3695,3053.93 3580,2938.93 3580,2786.88 3566.11,2772.99
NetU1_3: U1.3 U14.W13 | length 1374.2
  Layer 1 - Top Layer w8: U1.3@3385.59,3605.71 3385.59,3559.41 v2(3395,3550)
  Layer 8 - Bottom Layer w5: U14.W13@3552.17,2666.46 3552.17,2680.07
  Layer 8 - Bottom Layer w5.5: v2(3395,3550) 3655,3550 3810,3395 3810,3245 3676.97,3111.97 3676.97,3057.11 3565,2945.15 3565,2787.98 3555.11,2778.09 3555.11,2718.55 3555.18,2718.48 3555.18,2689.85 3552.17,2686.84 3552.17,2680.07
NetU5_B15: U5.B15 U5.D15 | length 2704.7
  Layer 1 - Top Layer w10: U5.D15@2578.35,1782.87 2580.17,1781.05 cw(c2566.12,1767.01) 2585.98,1767.01 cw(c2561.84,1767.01) 2578.91,1749.94 2569.27,1740.29 ccw(c2637.55,1672.01) 2540.98,1672.01 2540.98,1534.33 cw(c2498.66,1534.33) 2498.66,1492.01 2320.98,1492.01 ccw(c2320.98,1467.01) 2295.98,1467.01 2295.98,1447.01 ccw(c2320.98,1447.01) 2320.98,1422.01 2515.98,1422.01 cw(c2515.98,1397.01) 2540.98,1397.01 2540.98,1377.01 cw(c2515.98,1377.01) 2515.98,1352.01 2320.98,1352.01 ccw(c2320.98,1327.01) 2295.98,1327.01 2295.98,1307.01 ccw(c2320.98,1307.01) 2320.98,1282.01 2515.98,1282.01 cw(c2515.98,1257.01) 2540.98,1257.01 2540.98,1237.01 cw(c2515.98,1237.01) 2515.98,1212.01 2320.98,1212.01 ccw(c2320.98,1187.01) 2295.98,1187.01 2295.98,1167.01 ccw(c2320.98,1167.01) 2320.98,1142.01 2566.55,1142.01 ccw(c2566.55,1186.44) 2610.98,1186.44 2610.98,1681.65 cw(c2696.34,1681.65) 2635.98,1742.01 ccw(c2623.91,1754.08) 2640.98,1754.08 2640.98,1762.01 ccw(c2618.27,1762.01) 2634.33,1778.07 U5.B15@2629.53,1782.87
nRESET: J3.15 R125.1 | length 94.9
  Layer 8 - Bottom Layer w8: J3.15@4821.5,2950 R125.1@4916.38,2950
nTRST: J3.2 R111.2 | length 94.9
  Layer 8 - Bottom Layer w8: R111.2@4513.62,3300 J3.2@4608.5,3300
PMIC_ENABLE: J9.9 R83.1 U21.8 | length 1177.7
  Layer 1 - Top Layer w8: R83.1@1298.62,316.5 1298.88,316.75 J9.9@1375.73,316.75
  Layer 5 - Signal w5: J9.9@1375.98,317.01 1425.99,267 1592,267 1650,325 1650,426.23 1688.77,465 1750,465 1880,595 1980,595 2031,646 v2(2140,646)
  Layer 8 - Bottom Layer w8: U21.8@2042.6,650.94 2067.06,650.94 2072,646 v2(2140,646)
PMIC_GPIO1: J9.27 R218.1 R221.1 U21.1 | length 1042.7
  Layer 5 - Signal w5: J9.27@1375.98,917.01 1425.98,967 1623,967 1675,915 1755,915 1860,810 2010,810 2040,840 2108.88,840 v2(2146.38,802.5)
  Layer 8 - Bottom Layer w8: U21.1@2042.6,791.69 2113.31,791.69 2125,780 R221.1@2146.38,780 v2(2146.38,802.5) R218.1@2146.38,825 ; 2050,795 2055,795
PMIC_nINT_OUT: J9.6 R224.1 U14.B19 U21.9 | length 5741.3
  Layer 3 - Signal (Sensitive) w5: v2(2215,610) 2215,611.88 2233.12,630 2260,630 2285,655 2285,925 2145,1065 2145,1175 1970,1350 1970,1595 1920,1645 1750,1645 1705,1690 1705,2150 1735,2180 1950,2180 2075,2305 2125,2305 2155,2335 2900,2335 2930,2305 3040,2305 3190,2155 3498.79,2155 3553.79,2210 3680,2210 3700,2230 3755,2230 v7(3800,2185)
  Layer 5 - Signal w5: J9.6@1375.98,217.01 1427.99,165 1955,165 2060,270 2060,390 2120,450 2120,520 2100,540 2100,580 2127.5,607.5 2137.5,607.5 v2(2140,610)
  Layer 8 - Bottom Layer w5.5: U14.B19@3705.71,2231.42 3721.45,2231.42 3747.86,2205 3780,2205 v7(3800,2185)
  Layer 8 - Bottom Layer w8: U21.9@2042.6,628.31 2121.69,628.31 v2(2140,610) 2165,585 R224.1@2165,553.62 2188.81,553.62 2215,579.81 v2(2215,610)
PRE_REG_EN: J9.36 R205.2 | length 793.3
  Layer 5 - Signal w10: v2(820,1160) 820,1270 855,1305 1287.99,1305 J9.36@1375.98,1217.01
  Layer 8 - Bottom Layer w10: R205.2@775,1113.62 775,1134.31 787.72,1147.02 807.02,1147.02 v2(820,1160)
PRE_REG_PG: R83.2 R215.1 U20.10 | length 1170.9
  Layer 1 - Top Layer w8: v2(1210,316.5) R83.2@1251.38,316.5
  Layer 5 - Signal w5: v2(810,925) 710,825 710,475 780,405 921.5,405 1010,316.5 v2(1210,316.5)
  Layer 8 - Bottom Layer w8: R215.1@768.62,925 v2(810,925) 830,905 832.66,905 U20.10@832.77,905.12
QSPI_D0_FLASH: R134.1 U3.5 U15.5 | length 370.3
  Layer 1 - Top Layer w8: v2(1775,2695) 1825,2745 1895,2745 1920,2720 1920,2670 1879.53,2629.53 U3.5@1879.53,2602.24
  Layer 8 - Bottom Layer w8: U15.5@1775,2662.34 R134.1@1775,2722.01
QSPI_D1_FLASH: R148.2 U3.2 U15.2 | length 282.7
  Layer 1 - Top Layer w8: U3.2@1840.16,2507.76 1840.16,2480.16 1800,2440 1800,2395 1815,2380 1845,2380 v2(1875,2410)
  Layer 8 - Bottom Layer w8: R148.2@1875,2387.99 U15.2@1875,2447.66
QSPI_D2_FLASH: R149.2 U3.3 U15.3 | length 171.9
  Layer 1 - Top Layer w8: v2(1825,2410) 1825,2440 1859.84,2474.84 U3.3@1859.84,2507.76
  Layer 8 - Bottom Layer w8: R149.2@1825,2387.99 U15.3@1825,2447.66
QSPI_D3_FLASH: R132.1 U3.7 U15.7 | length 166.9
  Layer 1 - Top Layer w8: U3.7@1840.16,2602.24 1840.16,2660.16 v2(1875,2695)
  Layer 8 - Bottom Layer w8: U15.7@1875,2662.34 R132.1@1875,2722.01
QSPI_nCE_FLASH_A: R150.1 R234.1 U15.1 | length 87.8
  Layer 8 - Bottom Layer w8: U15.1@1925,2447.66 1925.16,2447.5 1925.16,2360.16 R234.1@1925.31,2360
QSPI_nCE_FLASH_B: R235.1 R240.1 U3.1 | length 330.5
  Layer 1 - Top Layer w8: U3.1@1820.47,2507.76 1820.47,2490.47 1750,2420 1750,2380 1770,2360 1880,2360 R235.1@1915.31,2360
QSPI_SCLK_FLASH: R133.1 U3.6 U15.6 | length 273.6
  Layer 1 - Top Layer w8: v2(1825,2695) 1850,2720 1890,2720 1900,2710 1900,2680 1859.84,2639.84 U3.6@1859.84,2602.24
  Layer 8 - Bottom Layer w8: U15.6@1825,2662.34 R133.1@1825,2722.01
RBOOT: R222.2 U20.3 | length 181.9
  Layer 8 - Bottom Layer w8: R222.2@823.62,650 825,651.38 825,667 835,677 835,722 843,730 863,730 897.73,764.73 U20.3@897.73,789.45
RCSS_UARTA_RX: TP19.1 U14.B16 | length 374.7
  Layer 8 - Bottom Layer w4: U14.B16@3628.94,2231.42 3641.73,2218.62 3641.73,2194.04
  Layer 8 - Bottom Layer w5.5: 3641.73,2194.04 3641.73,2187.27 3700,2129 3816,2129 3835,2110 TP19.1@3935,2110
RCSS_UARTA_TX: TP18.1 U14.A17 | length 559.6
  Layer 8 - Bottom Layer w4: 3654.53,2192.47 U14.A17@3654.53,2205.83
  Layer 8 - Bottom Layer w5.5: 3654.53,2192.47 3705,2142 3962,2142 3994,2174 3994,2229 4004,2239 4078,2239 4084,2245 TP18.1@4105,2245
RGMII_RCLK: R89.1 U14.M19 | length 3766.7
  Layer 3 - Signal (Sensitive) w5: v2(2995,3570) 3060,3635 3150,3635 3190,3595 3270,3595 3305,3630 3765,3630 3985,3410 3985,2705 3875,2595 3875,2560 v7(3825,2510)
  Layer 8 - Bottom Layer w5.5: U14.M19@3705.71,2487.32 3707,2486.03 3801.03,2486.03 v7(3825,2510)
  Layer 8 - Bottom Layer w8: R89.1@1945,3692.99 2217.01,3692.99 2380,3530 2406,3530 2419.25,3543.25 2419.25,3565 2429.25,3575 2449.25,3575 2459.25,3565 2459.25,3540 2469.25,3530 2499.4,3530 2509.4,3540 2509.4,3565 2519.4,3575 2539.4,3575 2549.4,3565 2549.4,3540 2559.4,3530 2589.55,3530 2599.55,3540 2599.55,3565 2609.55,3575 2629.55,3575 2639.55,3565 2639.55,3540 2649.55,3530 2679.7,3530 2689.7,3540 2689.7,3565 2699.7,3575 2719.7,3575 2729.7,3565 2729.7,3540 2739.7,3530 2769.85,3530 2779.85,3540 2779.85,3565 2789.85,3575 2809.85,3575 2819.85,3565 2819.85,3540 2829.85,3530 2860,3530 2870,3540 2870,3565 2880,3575 2900,3575 2910,3565 2910,3540 2920,3530 2955,3530 v2(2995,3570)
RGMII_RCTL: R98.1 U14.J17 | length 3778.9
  Layer 3 - Signal (Sensitive) w5: v2(1485,3512.99) 1552.01,3512.99 1565,3500 1670,3500 1705,3535 1820,3535 1850,3505 1850,3470 1865,3455 1890,3455 1905,3470 1905,3553 1917,3565 1960,3565 1990,3535 2065,3535 2145,3455 3785,3455 3860,3380 3860,2765 3710,2615 3710,2442.58 v5(3665.18,2397.76)
  Layer 8 - Bottom Layer w4: U14.J17@3654.53,2410.55 v5(3665.18,2397.76)
  Layer 8 - Bottom Layer w8: v2(1485,3512.99) R98.1@1565,3512.99
RGMII_RD0: R90.1 U14.P18 | length 3696.9
  Layer 3 - Signal (Sensitive) w5: v2(3075,3545) 3120,3545 3145,3520 3780,3520 3910,3390 3910,2717 3820,2627 v7(3820,2600)
  Layer 8 - Bottom Layer w4: U14.P18@3680.12,2538.5 3692.91,2551.3 3712.58,2551.3
  Layer 8 - Bottom Layer w5.5: 3712.58,2551.3 3715.28,2554 3747,2554 3755,2546 3776,2546 3810,2580 3810,2590 v7(3820,2600)
  Layer 8 - Bottom Layer w8: R90.1@1900,3692.99 1900,3725 1910,3735 2410,3735 2425,3720 2425,3625 2440,3610 2465,3610 2480,3625 2480,3720 2495,3735 2520,3735 2535,3720 2535,3625 2550,3610 2575,3610 2590,3625 2590,3720 2605,3735 2630,3735 2645,3720 2645,3625 2660,3610 2685,3610 2706,3631 2744,3631 2765,3610 3010,3610 v2(3075,3545)
RGMII_RD1: R91.1 U14.N19 | length 3714.7
  Layer 3 - Signal (Sensitive) w5: v2(3075,3605) 3140,3605 3175,3570 3280,3570 3315,3605 3755,3605 3960,3400 3960,2710 3860,2610 3860,2575 v7(3825,2540)
  Layer 8 - Bottom Layer w5.5: U14.N19@3705.71,2512.91 3715.91,2502.71 3730.06,2502.71 3747.35,2520 3805,2520 v7(3825,2540)
  Layer 8 - Bottom Layer w8: R91.1@1855,3692.99 1855,3740 1885,3770 2690,3770 2705,3755 2705,3731 2716,3720 2738,3720 2750,3732 2750,3755 2765,3770 2790,3770 2805,3755 2805,3665 2825,3645 2850,3645 2870,3665 2870,3755 2885,3770 2910,3770 2955,3725 2955,3665 2975,3645 3035,3645 v2(3075,3605)
RGMII_RD2: R92.1 U14.M18 | length 3733.3
  Layer 3 - Signal (Sensitive) w5.5: v2(3190,3670) 3220,3700 3275,3700 3320,3655 3775,3655 4010,3420 4010,2700 3890,2580 3890,2545 v7(3875,2530)
  Layer 8 - Bottom Layer w4: U14.M18@3680.12,2487.32 3692.91,2474.53 3717.49,2474.53
  Layer 8 - Bottom Layer w5.5: 3717.49,2474.53 3819.53,2474.53 v7(3875,2530)
  Layer 8 - Bottom Layer w8: R92.1@1810,3692.99 1810,3750 1865,3805 2945,3805 3157,3593 3175,3593 3190,3608 v2(3190,3670)
RGMII_RD3: R93.1 U14.L19 | length 3743.9
  Layer 3 - Signal (Sensitive) w5: v2(3160,3700) 3185,3725 3285,3725 3330,3680 3785,3680 4035,3430 4035,2695 3905,2565 3905,2530 v7(3855,2480)
  Layer 8 - Bottom Layer w5.5: U14.L19@3705.71,2461.73 3707,2463.03 3838.03,2463.03 v7(3855,2480)
  Layer 8 - Bottom Layer w8: R93.1@1765,3692.99 1765,3763 1842,3840 2990,3840 3130,3700 v2(3160,3700)
RGMII_TCLK: R94.1 U14.K19 | length 3780.9
  Layer 3 - Signal (Sensitive) w5: v2(2105,3620) 2117,3608 2117,3587 2105,3575 2105,3559 2119,3545 2150,3545 2160,3555 2160,3570 2170,3580 2185,3580 2195,3570 2195,3555 2205,3545 2225,3545 2235,3555 2235,3570 2245,3580 2260,3580 2270,3570 2270,3555 2280,3545 2890,3545 3030,3685 3065,3685 3155,3775 3305,3775 3350,3730 3800,3730 4085,3445 4085,2685 3935,2535 3935,2500 v7(3885,2450)
  Layer 8 - Bottom Layer w5.5: U14.K19@3705.71,2436.14 3717.15,2436.14 3720.77,2439.76 3874.76,2439.76 v7(3885,2450)
  Layer 8 - Bottom Layer w8: R94.1@2032.99,3620 2032.99,3647.99 2045,3660 2090,3660 2105,3645 v2(2105,3620)
RGMII_TCTL: R95.1 U14.J18 | length 3790
  Layer 3 - Signal (Sensitive) w5: v2(2060,3580) 2075,3595 2075,3632 2098,3655 2930,3655 3010,3735 3045,3735 3135,3825 3330,3825 3375,3780 3820,3780 4135,3465 4135,2675 3965,2505 3965,2475 3915,2425 v7(3915,2390)
  Layer 8 - Bottom Layer w4: U14.J18@3680.12,2410.55 3692.91,2397.76 3723.6,2397.76
  Layer 8 - Bottom Layer w5.5: 3723.6,2397.76 3731.11,2405.26 3899.74,2405.26 v7(3915,2390)
  Layer 8 - Bottom Layer w8: R95.1@2032.99,3580 v2(2060,3580)
RGMII_TD0: R104.1 U14.L18 | length 3824
  Layer 3 - Signal (Sensitive) w5: v2(2130,3510) 2140,3520 2900,3520 3040,3660 3075,3660 3165,3750 3295,3750 3340,3705 3795,3705 4060,3440 4060,2690 3920,2550 3920,2515 v7(3905,2500)
  Layer 8 - Bottom Layer w4: U14.L18@3680.12,2461.73 3692.91,2448.94 3714.38,2448.94
  Layer 8 - Bottom Layer w5.5: 3714.38,2448.94 3716.97,2451.53 3856.53,2451.53 v7(3905,2500)
  Layer 8 - Bottom Layer w8: R104.1@2032.99,3420 2070,3420 2080,3410 2235,3410 2245,3420 2245,3440 2235,3450 2145,3450 2130,3465 v2(2130,3510)
RGMII_TD1: R102.1 U14.L17 | length 3814.8
  Layer 3 - Signal (Sensitive) w5: v2(2060,3460) 2080,3440 2080,3380 2117.35,3342.65 2177.35,3342.65 2210,3310 2210,3265 2225,3250 2255,3250 2270,3265 2270,3330 2285,3345 2310,3345 2325,3330 2325,3265 2340,3250 2370,3250 2385,3265 2385,3330 2400,3345 2425,3345 2440,3330 2440,3265 2455,3250 2480,3250 2495,3265 2495,3330 2510,3345 2535,3345 2550,3330 2550,3265 2565,3250 2590,3250 2605,3265 2605,3330 2620,3345 2645,3345 2660,3330 2660,3265 2675,3250 2700,3250 2715,3265 2715,3330 2730,3345 2755,3345 2770,3330 2770,3265 2785,3250 2810,3250 2825,3265 2825,3330 2900,3405 3775,3405 3810,3370 3810,2860 3684,2734 3684,2467.76 v5(3665.18,2448.94)
  Layer 8 - Bottom Layer w4: U14.L17@3654.53,2461.73 3654.53,2459.59 v5(3665.18,2448.94)
  Layer 8 - Bottom Layer w8: R102.1@2032.99,3460 v2(2060,3460)
RGMII_TD2: R99.1 U14.K16 | length 3805.8
  Layer 3 - Signal (Sensitive) w5: v2(2060,3500) 2105,3455 2105,3385 2120,3370 2135,3370 2145,3380 2145,3420 2155,3430 2170,3430 2180,3420 2180,3380 2190,3370 2205,3370 2215,3380 2215,3420 2225,3430 2240,3430 2250,3420 2250,3380 2260,3370 2275,3370 2285,3380 2285,3420 2295,3430 2310,3430 2320,3420 2320,3380 2330,3370 2345,3370 2355,3380 2355,3420 2365,3430 2380,3430 2390,3420 2390,3380 2400,3370 2415,3370 2425,3380 2425,3420 2435,3430 2450,3430 2460,3420 2460,3380 2470,3370 2485,3370 2495,3380 2495,3420 2505,3430 2520,3430 2530,3420 2530,3380 2540,3370 2555,3370 2565,3380 2565,3420 2575,3430 2590,3430 2600,3420 2600,3380 2610,3370 2625,3370 2635,3380 2635,3420 2645,3430 2660,3430 2670,3420 2670,3380 2680,3370 2695,3370 2705,3380 2705,3422 2713,3430 3780,3430 3835,3375 3835,2765 3697,2627 3697,2452 3670,2425 3655,2425 3645.78,2434.22 v5(3645.78,2434.44)
  Layer 8 - Bottom Layer w5.1: U14.K16@3628.94,2436.14 3644.08,2436.14 v5(3645.78,2434.44)
  Layer 8 - Bottom Layer w8: R99.1@2032.99,3500 v2(2060,3500)
RGMII_TD3: R97.1 U14.K18 | length 3796.8
  Layer 3 - Signal (Sensitive) w5: v2(2165,3610) 2290,3610 2300,3600 2300,3580 2310,3570 2325,3570 2335,3580 2335,3600 2345,3610 2360,3610 2370,3600 2370,3580 2380,3570 2395,3570 2405,3580 2405,3600 2415,3610 2430,3610 2453,3587 2467,3587 2490,3610 2920,3610 3020,3710 3055,3710 3145,3800 3315,3800 3360,3755 3810,3755 4110,3455 4110,2680 3950,2520 3950,2485 v7(3915,2450)
  Layer 8 - Bottom Layer w4: U14.K18@3680.12,2436.14 3692.91,2423.35 3718.42,2423.35
  Layer 8 - Bottom Layer w5.5: 3718.42,2423.35 3723.33,2428.26 3893.26,2428.26 v7(3915,2450)
  Layer 8 - Bottom Layer w8: R97.1@2032.99,3540 2095,3540 v2(2165,3610)
RTCK: J3.9 R121.1 | length 94.1
  Layer 8 - Bottom Layer w8: J3.9@4821.5,3100 4913.62,3100 R121.1@4915,3098.62
RX_D0: R6.1 R90.2 U10.26 | length 217.5
  Layer 1 - Top Layer w8: v2(1900,3625) R6.1@1900,3656.38
  Layer 8 - Bottom Layer w8: U10.26@1804.06,3538.17 1804.06,3559.06 1825,3580 1855,3580 v2(1900,3625) R90.2@1900,3667.01
RX_D1: R5.1 R91.2 U10.25 | length 198.3
  Layer 1 - Top Layer w8: v2(1855,3625) R5.1@1855,3656.38
  Layer 8 - Bottom Layer w8: U10.25@1784.37,3538.17 1784.37,3569.37 1815,3600 1830,3600 v2(1855,3625) R91.2@1855,3667.01
RX_D2: R4.1 R92.2 U10.24 | length 179
  Layer 1 - Top Layer w8: v2(1810,3625) R4.1@1810,3656.38
  Layer 8 - Bottom Layer w8: U10.24@1764.68,3538.17 1764.68,3579.69 v2(1810,3625) R92.2@1810,3667.01
RX_D3: R3.1 R93.2 U10.23 | length 168.5
  Layer 1 - Top Layer w8: v2(1765,3625) R3.1@1765,3656.38
  Layer 8 - Bottom Layer w8: U10.23@1745,3538.17 1745,3605 v2(1765,3625) R93.2@1765,3667.01
RX_DV: R8.1 R98.2 U10.15 | length 133.6
  Layer 1 - Top Layer w8: R8.1@1565,3496.38 1565,3474 v2(1579,3460)
  Layer 8 - Bottom Layer w8: R98.2@1565,3487.01 1565,3474 v2(1579,3460) 1596,3460 1612.31,3443.69 U10.15@1630.83,3443.69
RX_ER: R9.1 U10.14 | length 122.2
  Layer 1 - Top Layer w8: R9.1@1520,3451.38 1521.38,3450 v2(1550,3450)
  Layer 8 - Bottom Layer w8: v2(1550,3450) 1563,3437 1596,3437 1609,3424 U10.14@1630.83,3424
SOC_I2C_SCL: J9.16 R76.1 U2.1 U8.1 U14.F18 | length 10135.3
  Layer 1 - Top Layer w8: J9.16@1575.98,617.01 1638.39,617.01 R76.1@1640,618.62 1640,622.56 1665.31,647.87 U8.1@1665.31,685.87 ; U2.1@4690.87,3464.69 v2(4690.87,3490)
  Layer 3 - Signal (Sensitive) w5: v7(3820,2305) 3830,2315 3955,2315 3970,2300 4009,2300 4040,2269 4069,2269 4080,2280 4080,2330 4120,2370 4270,2370 4340,2440 4340,2750 4430,2840 4550,2840 4620,2770 v7(5070,2770)
  Layer 5 - Signal w5: J9.16@1575.98,617.01 1525.98,567 1333,567 1295,529 1295,470 1295,86.72 1351.72,30 1645,30 1715,100 2641.72,100 2686.72,55 4460,55 5070,665 v7(5070,2770) 5070,2935 5080,2945 5080,3408.28 4953.28,3535 4735.87,3535 v2(4690.87,3490)
  Layer 8 - Bottom Layer w4: U14.F18@3680.12,2333.78 3692.91,2320.98 3719.91,2320.98
  Layer 8 - Bottom Layer w5.5: 3719.91,2320.98 3724.89,2316 3809,2316 v7(3820,2305)
SOC_I2C_SDA: J9.13 R81.1 U2.6 U8.6 U14.F16 | length 10138.5
  Layer 1 - Top Layer w8: R81.1@1640,471.38 1640,475.32 1636.06,471.38 1621.61,471.38 J9.13@1575.98,517.01 1525,567.99 1525,645 1547,667 1607,667 1625,685 1625,730 1639.13,744.13 U8.6@1665.31,744.13 ; U2.6@4749.13,3464.69 v2(4749.13,3490)
  Layer 3 - Signal (Sensitive) w5: v5(3640.81,2321.91) 3649.9,2331 3965,2331 3981,2315 4020,2315 4030,2325 4030,2360 4055,2385 4265,2385 4325,2445 4325,2760 4425,2860 4560,2860 4620,2800 v7(5045,2800)
  Layer 5 - Signal w5: J9.13@1575.98,517.01 1524.98,466 1351,466 1315,430 1315,95 1360,50 1636.72,50 1706.72,120 2650,120 2695,75 4451.72,75 5045,668.28 v7(5045,2800) 5045,2940 5060,2955 5060,3400 4945,3515 4774.13,3515 v2(4749.13,3490)
  Layer 8 - Bottom Layer w10: U14.F16@3628.94,2333.78 v5(3640.81,2321.91)
SOC_LVDS_CLK_N: J2.46 U14.W7 | length 952
  Layer 3 - Signal (Sensitive) w4: v5(3211.89,3255) 3215.58,3251.31 cw(c3199.27,3235) 3222.33,3235 3222.33,3220.08 cw(c3146.05,3220.08) 3199.99,3166.13 ccw(c3224.14,3142) 3190,3142 ccw(c3212,3142) 3212,3120 3228.17,3120 ccw(c3228.17,3136.83) 3240.07,3124.93 cw(c3247.49,3117.52) 3247.49,3128 3267.31,3128 cw(c3267.31,3105.31) 3290,3105.31 ccw(c3317.31,3105.31) 3297.99,3086.01 3312.59,3071.41 cw(c3309.17,3068) 3314,3068 3314,3063.46 ccw(c3322.46,3063.46) 3322.46,3055 3326.54,3055 ccw(c3326.54,3063.46) 3335,3063.46 3335,3064.76 cw(c3345.24,3064.76) 3345.24,3075 3357.69,3075 cw(c3357.69,3047.69) 3385,3047.69 3385,3042 cw(c3373.5,3042) 3373.5,3030.5 cw(c3373.5,3049.81) 3359.84,3036.16 v5(3355,3041)
  Layer 8 - Bottom Layer w4: v5(3211.89,3255) 3211.89,3256 3221.61,3265.72 3221.61,3293.5 3219.5,3295.61 3219.5,3335.66 J2.46@3217.36,3337.8 ; v5(3355,3041) 3357.93,3038.07 ccw(c3375,3055.14) 3375,3031 3377.22,3031 cw(c3377.22,3000.22) 3408,3000.22 3408,2808.31 cw(c3380.69,2808.31) 3400,2789 ccw(c3407.66,2781.34) 3396.83,2781.34 3396.83,2680.23 3398.62,2678.43 U14.W7@3398.62,2666.46
SOC_LVDS_CLK_P: J2.44 U14.V7 | length 952.3
  Layer 3 - Signal (Sensitive) w4: v5(3242.52,3255) 3239.27,3251.76 ccw(c3256.03,3235) 3232.33,3235 3232.33,3220.06 cw(c3146.08,3220.06) 3207.07,3159.07 ccw(c3224.14,3142) 3200,3142 ccw(c3212,3142) 3212,3130 3228.17,3130 ccw(c3228.17,3136.83) 3233,3132 cw(c3247.49,3117.52) 3247.49,3138 3267.31,3138 cw(c3267.31,3105.31) 3300,3105.31 ccw(c3317.31,3105.31) 3305.07,3093.07 3310.07,3088.07 ccw(c3317.49,3095.49) 3317.49,3085 3357.69,3085 cw(c3357.69,3047.69) 3395,3047.69 3395,3042 cw(c3373.5,3042) 3373.5,3020.5 ccw(c3373.5,3001.19) 3359.84,3014.84 v5(3355.5,3010.5)
  Layer 8 - Bottom Layer w4: J2.44@3237.05,3337.8 3234.91,3335.66 3234.91,3295.61 3232.61,3293.31 3232.61,3265.91 3242.52,3256 v5(3242.52,3255) ; v5(3355.5,3010.5) 3357.93,3012.93 cw(c3375,2995.86) 3375,3020 3377.22,3020 cw(c3377.22,3000.22) 3397,3000.22 3397,2808.31 cw(c3380.69,2808.31) 3392.22,2796.78 ccw(c3407.66,2781.34) 3385.83,2781.34 3385.83,2661 ccw(c3403.54,2661) 3391.02,2648.46 U14.V7@3398.62,2640.87
SOC_LVDS_FRCLK_N: J2.28 U14.W8 | length 952.6
  Layer 3 - Signal (Sensitive) w4: v5(3389.06,3255) 3392.74,3251.31 cw(c3376.43,3235) 3399.5,3235 3399.5,3220.5 ccw(c3425,3220.5) 3425,3195 3485,3195 cw(c3485,3137) 3543,3137 3543,3030 cw(c3487,3030) 3487,2974 3483.75,2974 ccw(c3483.75,2945.25) 3455,2945.25 3455,2937.61 cw(c3443.87,2937.61) 3451.74,2929.74 3447.12,2925.12 ccw(c3452.24,2920) 3445,2920 3445,2909 ccw(c3452,2909) 3452,2902 3462.17,2902 ccw(c3462.17,2908.83) 3466.99,2903.99 3471.38,2908.38 cw(c3476.5,2903.26) 3476.5,2910.5 cw(c3476.5,2891.19) 3490.16,2904.84 v5(3495,2900)
  Layer 8 - Bottom Layer w4: v5(3389.06,3255) 3389.06,3256 3398.78,3265.72 3398.78,3293.5 3396.67,3295.61 3396.67,3335.66 J2.28@3394.53,3337.8 ; U14.W8@3424.21,2666.46 3424.21,2678.43 3422.42,2680.23 3422.42,2736.28 cw(c3451.72,2736.28) 3431,2757 3431.57,2757.57 ccw(c3399.13,2790) 3445,2790 3445,2882.22 cw(c3472.78,2882.22) 3472.78,2910 3475,2910 cw(c3475,2885.86) 3492.07,2902.93 v5(3495,2900)
SOC_LVDS_FRCLK_P: J2.26 U14.V8 | length 952.4
  Layer 3 - Signal (Sensitive) w4: v5(3419.69,3255) 3416.44,3251.76 ccw(c3433.2,3235) 3409.5,3235 3409.5,3220.5 ccw(c3425,3220.5) 3425,3205 3485,3205 cw(c3485,3137) 3553,3137 3553,3030 cw(c3487,3030) 3487,2964 3483.75,2964 ccw(c3483.75,2945.25) 3465,2945.25 3465,2929.14 ccw(c3473.64,2929.14) 3473.64,2920.5 3476.5,2920.5 ccw(c3476.5,2939.81) 3490.16,2926.16 v5(3494.5,2930.5)
  Layer 8 - Bottom Layer w4: J2.26@3414.21,3337.8 3412.07,3335.66 3412.07,3295.61 3409.78,3293.31 3409.78,3265.91 3419.69,3256 v5(3419.69,3255) ; U14.V8@3424.21,2640.87 3416.61,2648.46 cw(c3429.13,2661) 3411.42,2661 3411.42,2736.28 cw(c3451.72,2736.28) 3423.22,2764.78 3423.79,2765.34 ccw(c3399.13,2790) 3434,2790 3434,2882.22 cw(c3472.78,2882.22) 3472.78,2921 3475,2921 ccw(c3475,2945.14) 3492.07,2928.07 v5(3494.5,2930.5)
SOC_LVDS_TX0_N: J2.58 U14.V6 | length 952.7
  Layer 3 - Signal (Sensitive) w4: v5(3093.78,3255) 3097.47,3251.31 cw(c3081.16,3235) 3104.22,3235 cw(c3090.62,3235) 3100.24,3225.38 3067.78,3192.93 ccw(c3113.13,3147.58) 3049,3147.58 3049,3097.21 ccw(c3086.06,3097.21) 3059.86,3071 3094.2,3036.66 ccw(c3132,3074.46) 3132,3021 3187,3021 cw(c3187,3001.69) 3200.66,3015.34 v5(3205.5,3010.5)
  Layer 8 - Bottom Layer w4: v5(3093.78,3255) 3093.78,3256 3103.5,3265.72 3103.5,3293.5 3101.39,3295.61 3101.39,3335.66 J2.58@3099.25,3337.8 ; v5(3205.5,3010.5) 3207.93,3012.93 cw(c3225,2995.86) 3225,3020 3244.23,3020 cw(c3244.23,2931.23) 3307,2994 3330.95,2970.05 cw(c3260.24,2899.34) 3360.24,2899.34 3360.24,2661 ccw(c3377.95,2661) 3365.43,2648.46 U14.V6@3373.03,2640.87
SOC_LVDS_TX0_P: J2.56 U14.W6 | length 952.1
  Layer 3 - Signal (Sensitive) w4: v5(3124.41,3255) 3121.16,3251.76 ccw(c3137.92,3235) 3114.22,3235 cw(c3090.62,3235) 3107.32,3218.32 3074.85,3185.85 ccw(c3113.13,3147.58) 3059,3147.58 3059,3097.21 ccw(c3086.07,3097.21) 3066.93,3078.07 3101.27,3043.73 ccw(c3132,3074.46) 3132,3031 3146.17,3031 ccw(c3146.17,3038.83) 3154,3038.83 3154,3044.17 cw(c3160.83,3044.17) 3160.83,3051 3168.17,3051 cw(c3168.17,3044.17) 3175,3044.17 3175,3039.46 ccw(c3183.46,3039.46) 3183.46,3031 3187,3031 ccw(c3187,3050.31) 3200.66,3036.66 v5(3205,3041)
  Layer 8 - Bottom Layer w4: J2.56@3118.94,3337.8 3116.8,3335.66 3116.8,3295.61 3114.5,3293.31 3114.5,3265.91 3124.41,3256 v5(3124.41,3255) ; v5(3205,3041) 3207.93,3038.07 ccw(c3225,3055.14) 3225,3031 3244.23,3031 cw(c3244.23,2931.23) 3314.78,3001.78 3338.72,2977.83 cw(c3260.24,2899.34) 3371.24,2899.34 3371.24,2680.23 3373.03,2678.43 U14.W6@3373.03,2666.46
SOC_LVDS_TX1_N: J2.52 U14.V5 | length 951.9
  Layer 3 - Signal (Sensitive) w4: v5(3152.83,3255) 3156.52,3251.31 cw(c3140.21,3235) 3163.28,3235 ccw(c3188.1,3235) 3170.55,3217.45 3171,3217 cw(c3161.34,3207.34) 3175,3207.34 3175,3196 cw(c3164,3196) 3164,3185 3142.8,3185 ccw(c3142.8,3137.2) 3095,3137.2 3095,3122.42 ccw(c3137.42,3122.42) 3137.42,3080 3215.86,3080 cw(c3215.86,3045.86) 3250,3045.86 3250,3003 cw(c3230.69,3003) 3244.34,2989.34 v5(3239.5,2984.5)
  Layer 8 - Bottom Layer w4: v5(3152.83,3255) 3152.83,3256 3162.56,3265.72 3162.56,3293.5 3160.44,3295.61 3160.44,3335.66 J2.52@3158.31,3337.8 ; v5(3239.5,2984.5) 3241.93,2982.07 cw(c3224.86,2965) 3249,2965 3249,2962.78 ccw(c3266.78,2962.78) 3266.78,2945 3288,2945 cw(c3288,2909) 3324,2909 3324,2805.9 ccw(c3347.9,2805.9) 3331,2789 cw(c3322.2,2780.2) 3334.65,2780.2 3334.65,2661 ccw(c3352.36,2661) 3339.84,2648.46 U14.V5@3347.44,2640.87
SOC_LVDS_TX1_P: J2.50 U14.W5 | length 952.5
  Layer 3 - Signal (Sensitive) w4: v5(3183.46,3255) 3180.22,3251.76 ccw(c3196.97,3235) 3173.28,3235 ccw(c3188.1,3235) 3177.62,3224.52 3178.07,3224.07 cw(c3161.34,3207.34) 3185,3207.34 3185,3196 cw(c3164,3196) 3164,3175 3150,3175 3142.8,3175 ccw(c3142.8,3137.2) 3105,3137.2 3105,3122.42 ccw(c3137.42,3122.42) 3137.42,3090 3215.86,3090 cw(c3215.86,3045.86) 3260,3045.86 3260,3044.46 ccw(c3268.46,3044.46) 3268.46,3036 3275,3036 cw(c3275,3029) 3282,3029 3282,3022 cw(c3275,3022) 3275,3015 3270.24,3015 ccw(c3270.24,3004.76) 3260,3004.76 3260,3003 ccw(c3279.31,3003) 3265.66,2989.34 v5(3270,2985)
  Layer 8 - Bottom Layer w4: J2.50@3177.99,3337.8 3175.85,3335.66 3175.85,3295.61 3173.56,3293.31 3173.56,3265.91 3183.46,3256 v5(3183.46,3255) ; v5(3270,2985) 3267.07,2982.07 ccw(c3284.14,2965) 3260,2965 3260,2962.78 ccw(c3266.78,2962.78) 3266.78,2956 3288,2956 cw(c3288,2909) 3335,2909 3335,2805.9 ccw(c3347.9,2805.9) 3338.78,2796.78 cw(c3322.2,2780.2) 3345.65,2780.2 3345.65,2680.23 3347.44,2678.43 U14.W5@3347.44,2666.46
